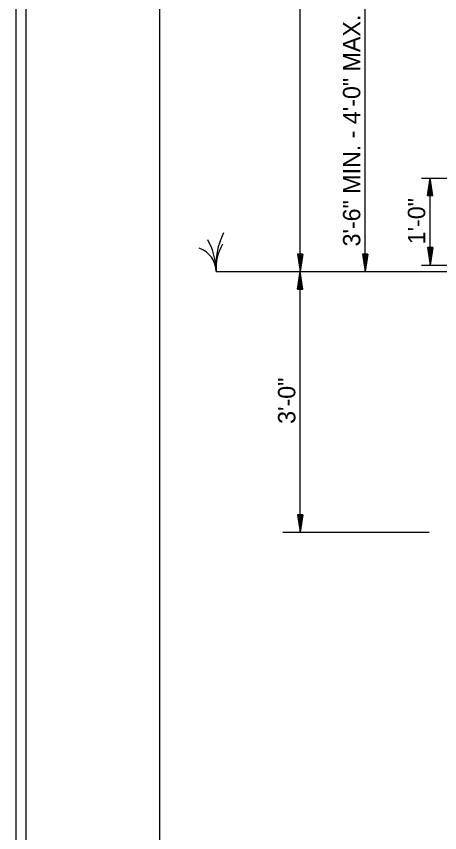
# Model space of a CAD drawing. Extents: x 1695551 to 1695718, y 544410 to 544516.
# Drawn here: x 1695551.26 to 1695569.58, y 544463.26 to 544498.53 of the extents above; entities that cross this region are included whole.
import ezdxf

# ---------------------------------------------------------------- set-up
doc = ezdxf.new("R2010")
doc.units = 0
for name, color, linetype in [('0_Plot Shape', 7, 'Continuous'), ('R_Border', 7, 'Continuous'), ('R_Draft', 7, 'Continuous'), ('R_No Plot', 7, 'Continuous')]:
    doc.layers.add(name, color=color, linetype=linetype)

msp = doc.modelspace()

# ---------------------------------------------------------------- linework, layer by layer
at = {"layer": '0_Plot Shape'}
msp.add_lwpolyline([(1695551.694, 544515.386), (1695716.694, 544515.386), (1695716.694, 544410.386), (1695551.694, 544410.386)], close=True, dxfattribs=at)
at = {"layer": 'R_Border'}
msp.add_line((1695557.469, 544411.521), (1695557.469, 544514.251), dxfattribs=at)
at = {"layer": 'R_Draft'}
for p, q in [((1695563.546, 544487.501), (1695563.546, 544510.601)), ((1695566.358, 544487.501), (1695566.358, 544502.501)), ((1695568.796, 544491.538), (1695570.98, 544491.538)), ((1695569.058, 544490.788), (1695569.171, 544491.538)), ((1695569.077, 544490.788), (1695569.171, 544491.413)), ((1695569.096, 544490.788), (1695569.171, 544491.284)), ((1695569.171, 544487.788), (1695569.171, 544491.538)), ((1695569.283, 544490.788), (1695569.171, 544491.538)), ((1695569.264, 544490.788), (1695569.171, 544491.413)), ((1695569.245, 544490.788), (1695569.171, 544491.284)), ((1695569.115, 544490.788), (1695569.171, 544491.159)), ((1695569.134, 544490.788), (1695569.171, 544491.032)), ((1695569.226, 544490.788), (1695569.171, 544491.159)), ((1695569.207, 544490.788), (1695569.171, 544491.032)), ((1695569.058, 544490.788), (1695569.283, 544490.788)), ((1695569.153, 544490.788), (1695569.171, 544490.907)), ((1695569.188, 544490.788), (1695569.171, 544490.907)), ((1695569.058, 544488.538), (1695569.171, 544487.788)), ((1695569.283, 544488.538), (1695569.058, 544488.538)), ((1695569.077, 544488.538), (1695569.171, 544487.913)), ((1695569.096, 544488.538), (1695569.171, 544488.042)), ((1695569.115, 544488.538), (1695569.171, 544488.167)), ((1695569.134, 544488.538), (1695569.171, 544488.294)), ((1695569.153, 544488.538), (1695569.171, 544488.42)), ((1695569.283, 544488.538), (1695569.171, 544487.788)), ((1695569.207, 544488.538), (1695569.171, 544488.294)), ((1695569.245, 544488.538), (1695569.171, 544488.042)), ((1695569.264, 544488.538), (1695569.171, 544487.913)), ((1695569.226, 544488.538), (1695569.171, 544488.167)), ((1695569.188, 544488.538), (1695569.171, 544488.42)), ((1695563.433, 544488.251), (1695563.546, 544487.501)), ((1695563.658, 544488.251), (1695563.433, 544488.251)), ((1695563.452, 544488.251), (1695563.546, 544487.626)), ((1695563.471, 544488.251), (1695563.546, 544487.755)), ((1695563.49, 544488.251), (1695563.546, 544487.88)), ((1695563.509, 544488.251), (1695563.546, 544488.007)), ((1695563.528, 544488.251), (1695563.546, 544488.133)), ((1695563.658, 544488.251), (1695563.546, 544487.501)), ((1695563.582, 544488.251), (1695563.546, 544488.007)), ((1695563.62, 544488.251), (1695563.546, 544487.755)), ((1695563.639, 544488.251), (1695563.546, 544487.626)), ((1695563.601, 544488.251), (1695563.546, 544487.88)), ((1695563.563, 544488.251), (1695563.546, 544488.133)), ((1695566.246, 544488.251), (1695566.358, 544487.501)), ((1695566.471, 544488.251), (1695566.246, 544488.251)), ((1695566.264, 544488.251), (1695566.358, 544487.626)), ((1695566.283, 544488.251), (1695566.358, 544487.755)), ((1695566.302, 544488.251), (1695566.358, 544487.88)), ((1695566.321, 544488.251), (1695566.358, 544488.007)), ((1695566.34, 544488.251), (1695566.358, 544488.133)), ((1695566.471, 544488.251), (1695566.358, 544487.501)), ((1695566.394, 544488.251), (1695566.358, 544488.007)), ((1695566.433, 544488.251), (1695566.358, 544487.755)), ((1695566.452, 544488.251), (1695566.358, 544487.626)), ((1695566.414, 544488.251), (1695566.358, 544487.88)), ((1695566.376, 544488.251), (1695566.358, 544488.133)), ((1695568.796, 544487.788), (1695570.98, 544487.788)), ((1695559.91, 544487.501), (1695599.544, 544487.501)), ((1695563.433, 544486.751), (1695563.546, 544487.501)), ((1695563.546, 544476.251), (1695563.546, 544487.501)), ((1695563.658, 544486.751), (1695563.546, 544487.501)), ((1695563.452, 544486.751), (1695563.546, 544487.376)), ((1695563.471, 544486.751), (1695563.546, 544487.247)), ((1695563.49, 544486.751), (1695563.546, 544487.122)), ((1695563.639, 544486.751), (1695563.546, 544487.376)), ((1695563.62, 544486.751), (1695563.546, 544487.247)), ((1695563.601, 544486.751), (1695563.546, 544487.122)), ((1695563.433, 544486.751), (1695563.658, 544486.751)), ((1695563.509, 544486.751), (1695563.546, 544486.995)), ((1695563.528, 544486.751), (1695563.546, 544486.87)), ((1695563.582, 544486.751), (1695563.546, 544486.995)), ((1695563.563, 544486.751), (1695563.546, 544486.87)), ((1695563.433, 544477.001), (1695563.546, 544476.251)), ((1695563.658, 544477.001), (1695563.433, 544477.001)), ((1695563.452, 544477.001), (1695563.546, 544476.377)), ((1695563.471, 544477.001), (1695563.546, 544476.506)), ((1695563.49, 544477.001), (1695563.546, 544476.63)), ((1695563.509, 544477.001), (1695563.546, 544476.758)), ((1695563.528, 544477.001), (1695563.546, 544476.883)), ((1695563.658, 544477.001), (1695563.546, 544476.251)), ((1695563.582, 544477.001), (1695563.546, 544476.758)), ((1695563.62, 544477.001), (1695563.546, 544476.506)), ((1695563.639, 544477.001), (1695563.546, 544476.377)), ((1695563.601, 544477.001), (1695563.546, 544476.63)), ((1695563.563, 544477.001), (1695563.546, 544476.883)), ((1695562.796, 544476.251), (1695569.124, 544476.251))]:
    msp.add_line(p, q, dxfattribs=at)
for centre, radius, start, end in [((1695563.056, 544487.777), 3.158, 153.6036, 185.017), ((1695557.041, 544487.481), 2.869, 0.407, 29.2294), ((1695558.824, 544487.482), 1.086, 1.0116, 71.214), ((1695561.9, 544487.664), 1.997, 149.1449, 184.6717)]:
    msp.add_arc(centre, radius, start, end, dxfattribs=at)
at = {"layer": 'R_No Plot'}
msp.add_lwpolyline([(1695551.265, 544516.198), (1695717.935, 544516.198), (1695717.935, 544409.529), (1695551.265, 544409.529)], close=True, dxfattribs=at)

# ---------------------------------------------------------------- texts
at = {"layer": 'R_Draft'}
for s, p in [('3\'-6" MIN. - 4\'-0" MAX.', (1695566.144, 544488.591)), ('1\'-0"', (1695568.951, 544488.684)), ('3\'-0"', (1695563.334, 544480.925))]:
    msp.add_text(s, height=0.75, rotation=90, dxfattribs=at).set_placement(p)

doc.saveas('drawing.dxf')
